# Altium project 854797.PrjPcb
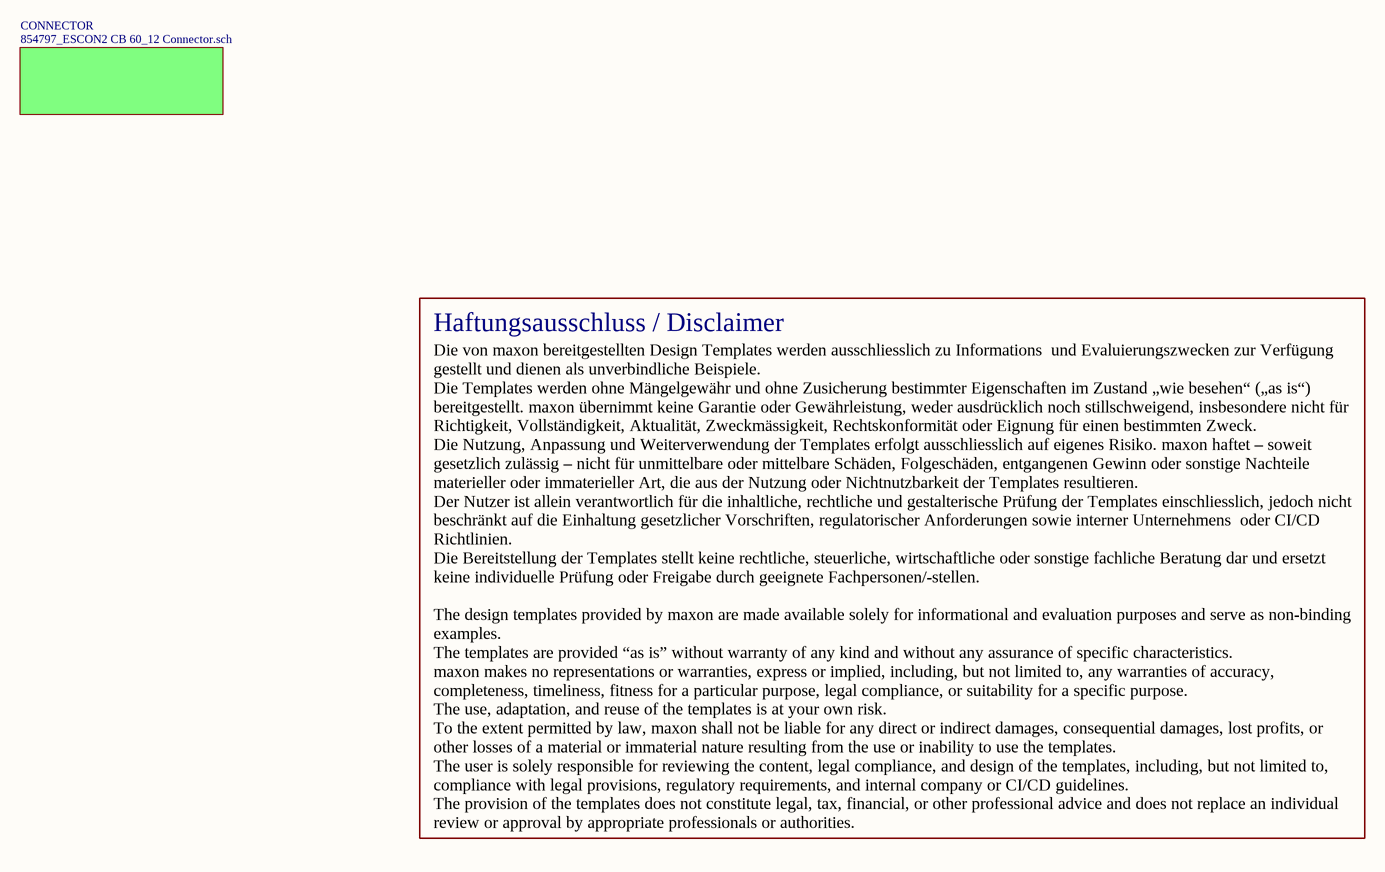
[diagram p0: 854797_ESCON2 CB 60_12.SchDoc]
CO_no: A100031416; Department: CCMC; ElecPCB: 121515, 12654, 45454, 45454; PCB Eng Rev: 03; PCB unassembled: 854797
1 sheet, 1 parts. Net scope: global (net labels, ports and power ports of the same name join across sheets).
Board file: ESCON2 CB 60_12.PcbDoc

## Sheet 854797_ESCON2 CB 60_12.SchDoc
size A3; SheetNumber: 1; SheetTotal: 2; Created: MMAGBCH; Modified: MMAGFLLU; Reviewed: MMAGBCH; CreatedDate: 19.02.2024; ReviewedDate: 07.03.2025

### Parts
*  Disclaimer  (value not drawn)  (graphical)

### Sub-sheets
CONNECTOR = 854797_ESCON2 CB 60_12 Connector.sch (file not in this document): no entries

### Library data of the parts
* = CMP-002918-3: Disclaimer Text according to IFS-Doc:13538260

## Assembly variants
854798: all parts fitted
